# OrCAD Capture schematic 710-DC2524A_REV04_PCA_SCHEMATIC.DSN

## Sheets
1 LTC5555 - Page 2: size Custom; note: PROGRAMMABLE GAIN MIXER
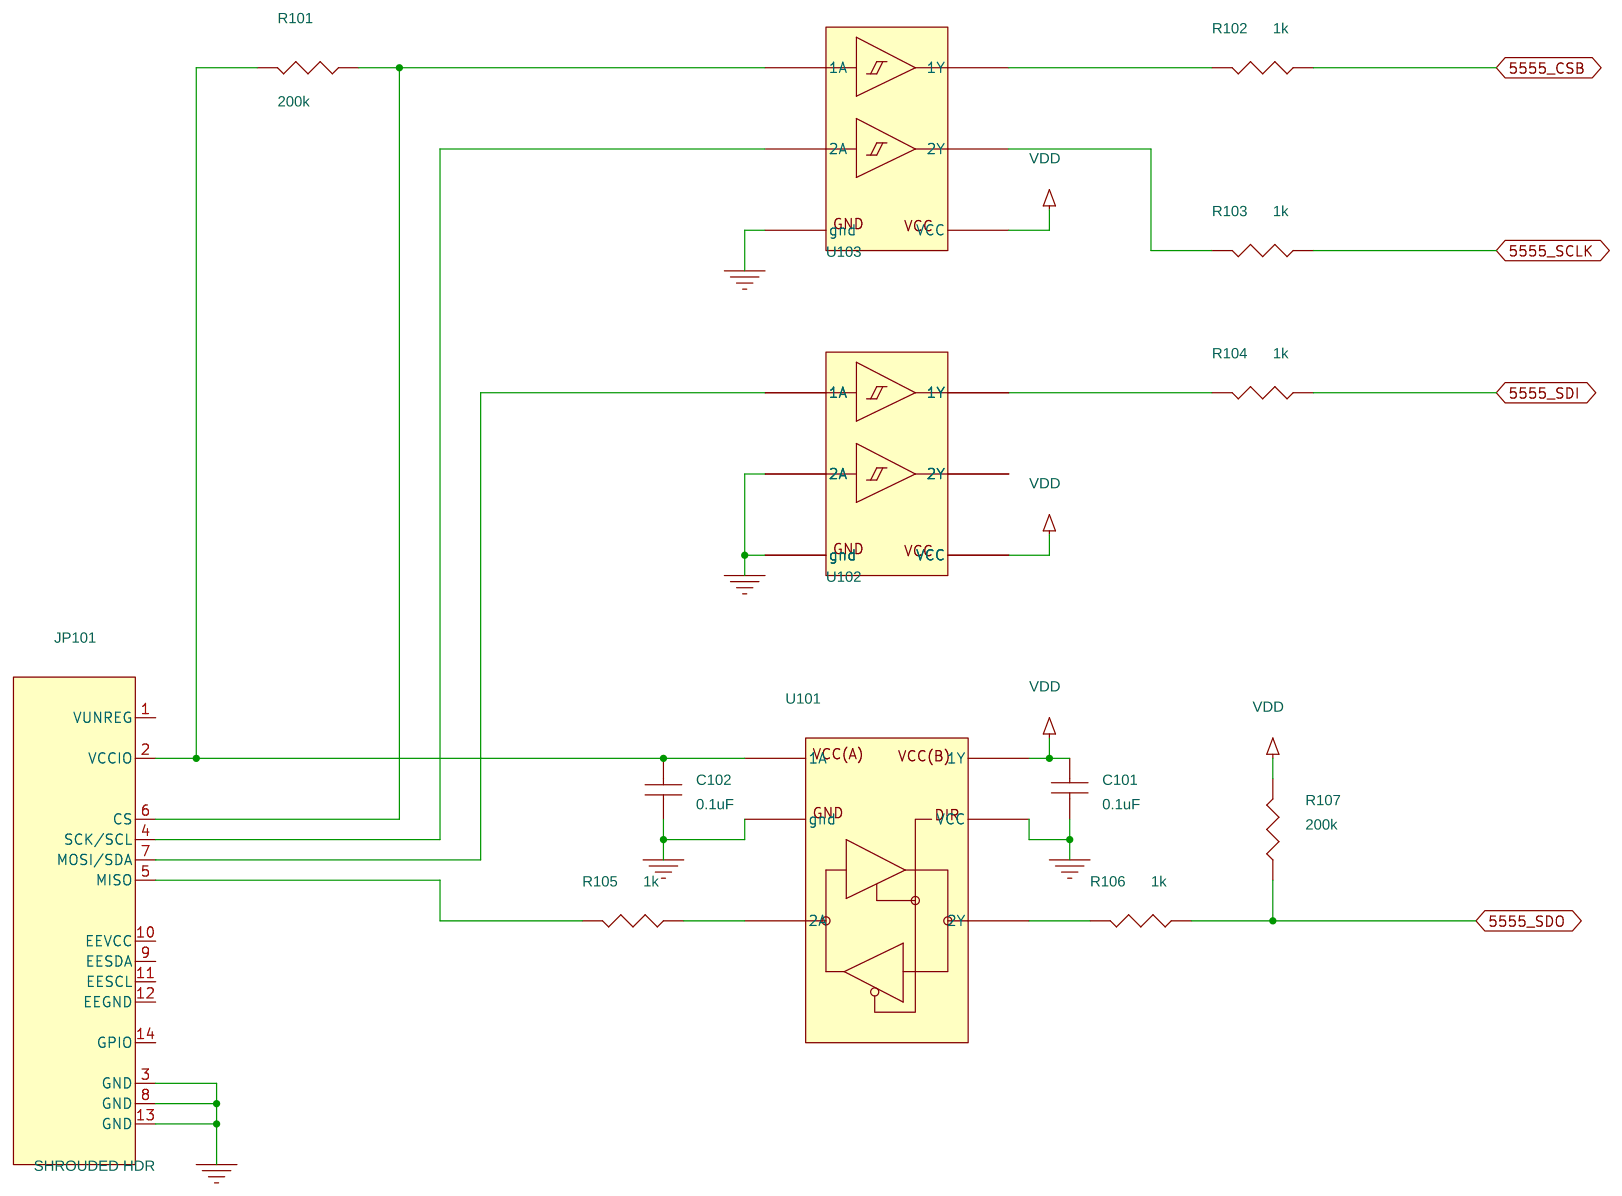
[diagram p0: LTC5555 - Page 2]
2 LTC5555 - Page 1: size Custom
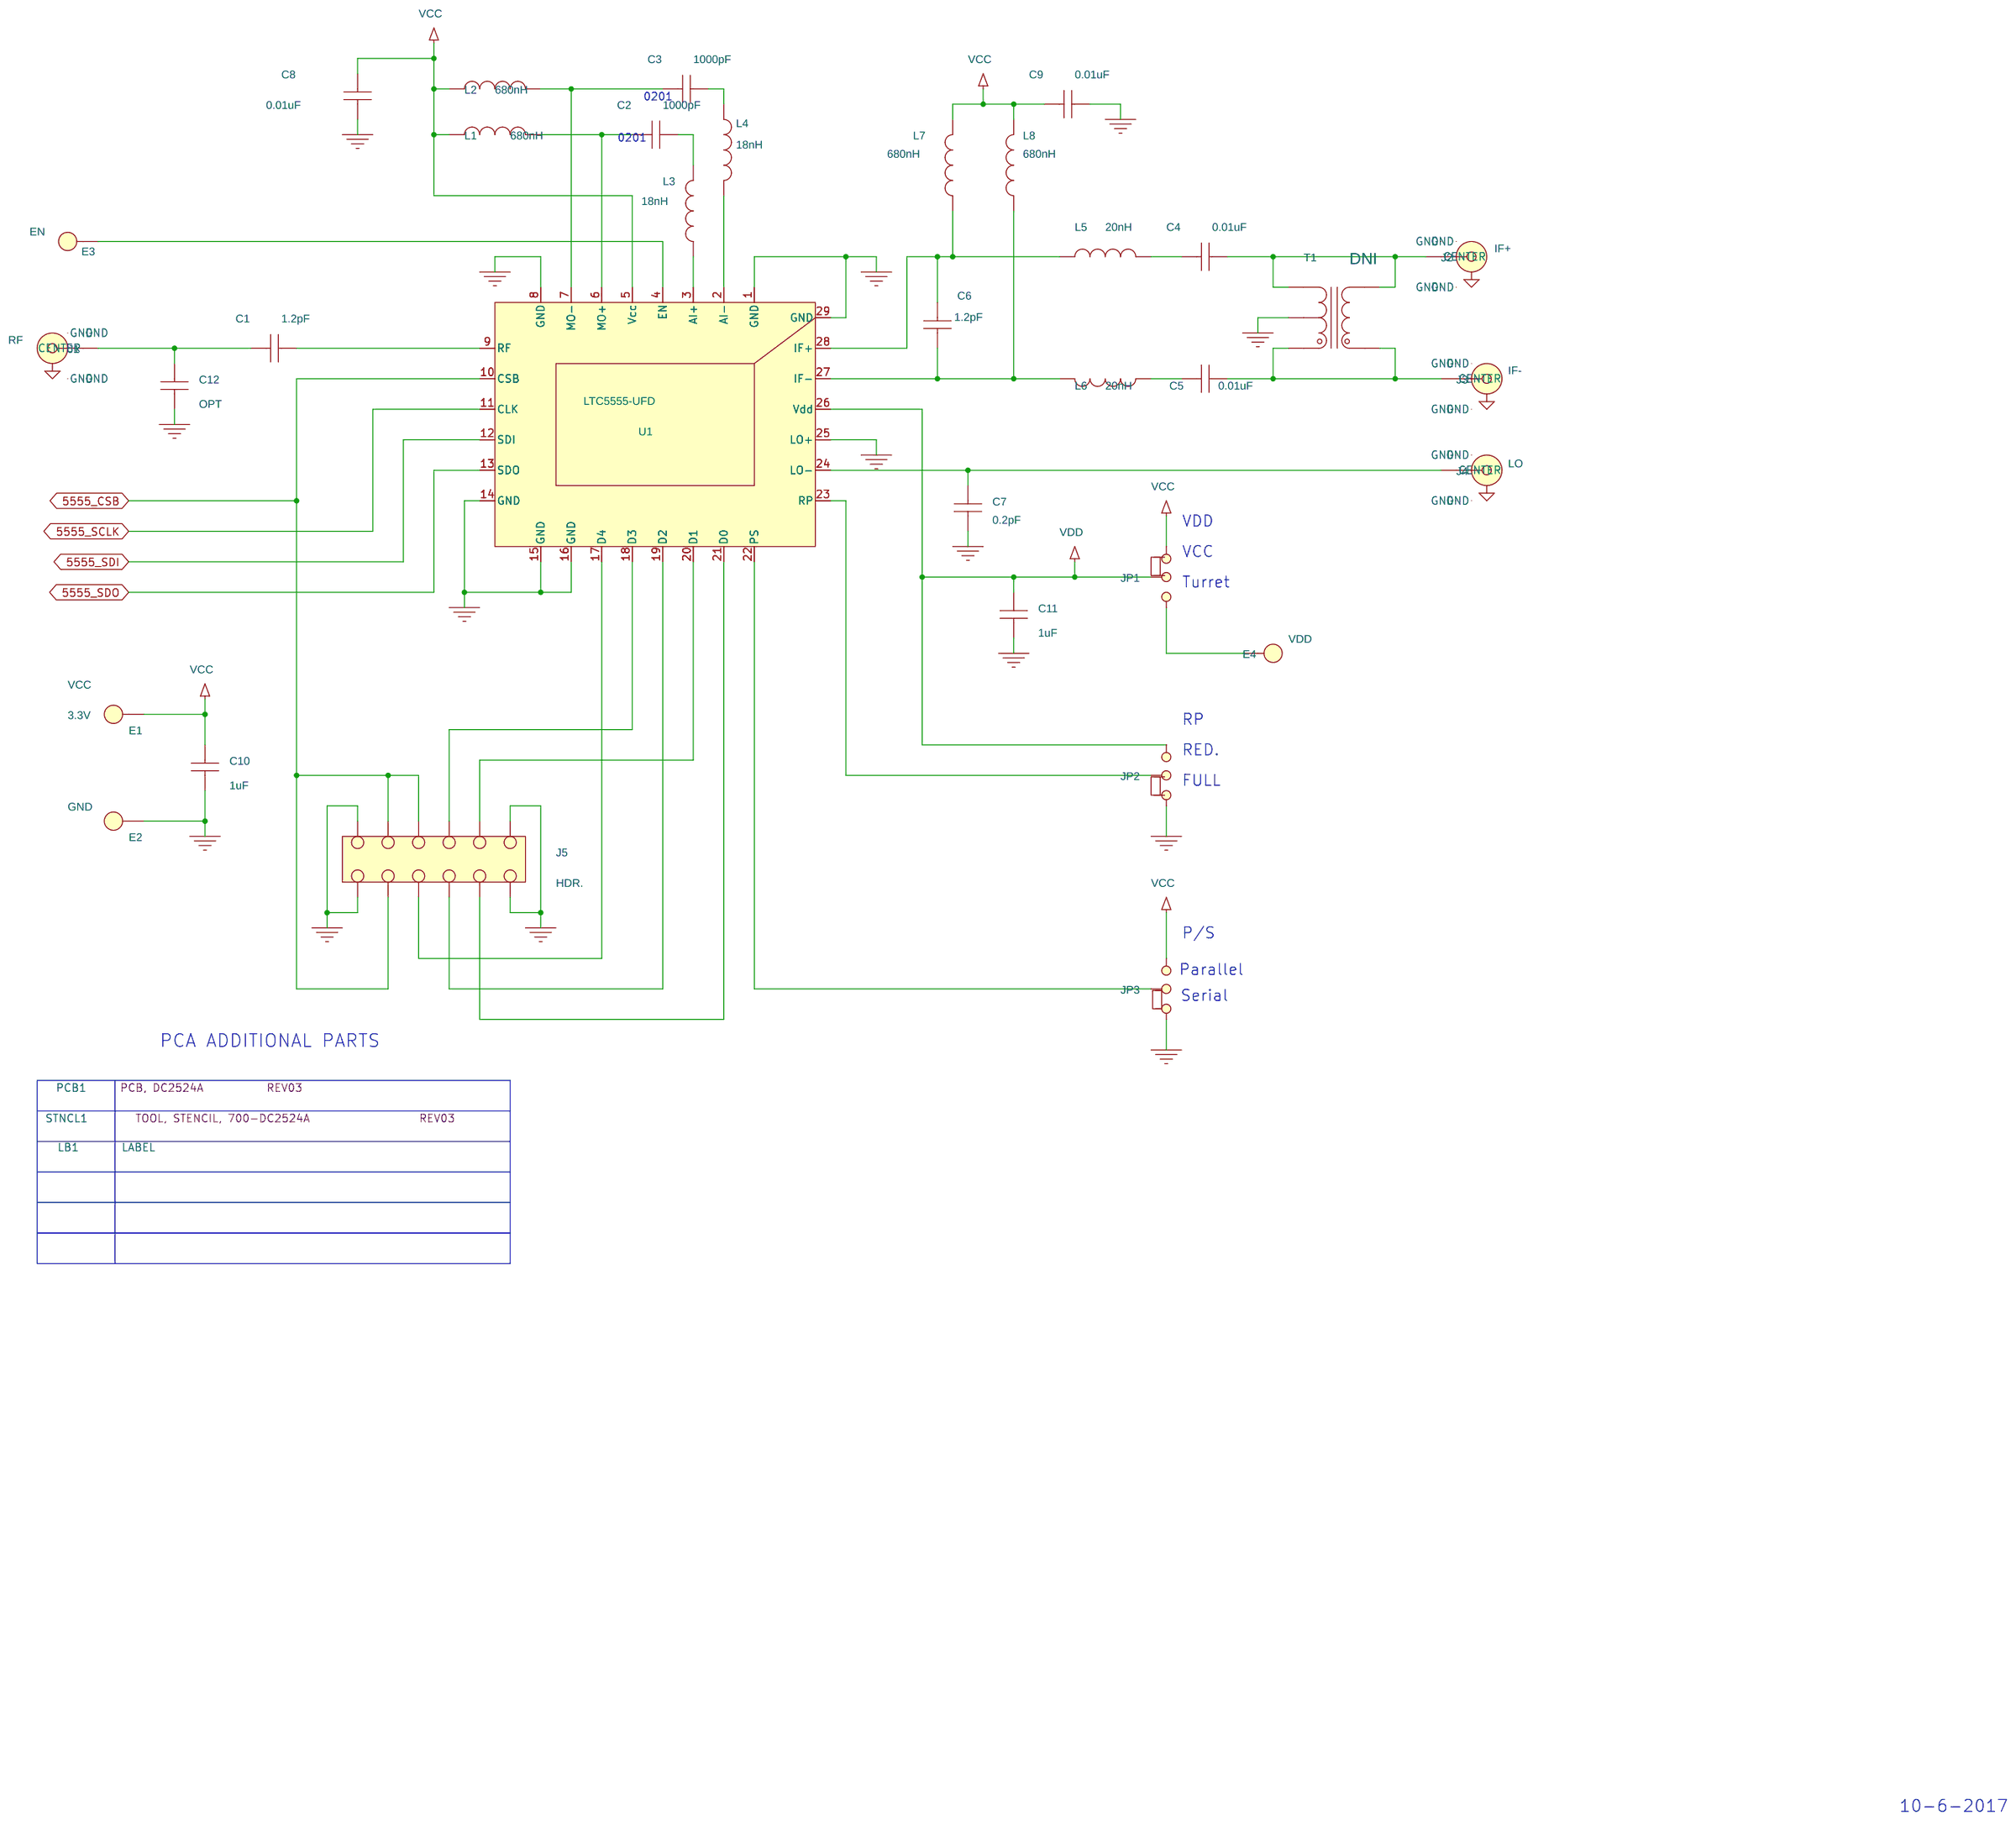
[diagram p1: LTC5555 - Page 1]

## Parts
sheet LTC5555 - Page 1
C1  1.2pF  [CC0402N]
C2  1000pF  [CC0201N]
C3  1000pF  [CC0201N]
C4  0.01uF  [CC0402N]
C5  0.01uF  [CC0402N]
C6  1.2pF  [CC0402N]
C7  0.2pF  [CC0201N]
C8  0.01uF  [CC0402N]
C9  0.01uF  [CC0402N]
C10  1uF  [CC0603N]
C11  1uF  [CC0603N]
C12  OPT  [CC0402N]
E1  TEST POINT  [MILLMAX2308]
E2  TEST POINT  [MILLMAX2308]
E3  TEST POINT  [MILLMAX2308]
E4  TEST POINT  [MILLMAX2308]
J1  SMA  [EMERSON_142-0701-851]
J2  SMA  [EMERSON_142-0701-851]
J3  SMA  [EMERSON_142-0701-851]
J4  SMA  [EMERSON_142-0701-851]
J5  HDR.  [HDR2X6-100-SM]
JP1  HDR.  [HD1X3-079]
JP2  HDR.  [HD1X3-079]
JP3  HDR.  [HD1X3-079]
L1  680nH  [IND0603N]
L2  680nH  [IND0603N]
L3  18nH  [IND0402N]
L4  18nH  [IND0402N]
L5  20nH  [IND0402N]
L6  20nH  [IND0402N]
L7  680nH  [IND0603N]
L8  680nH  [IND0603N]
LB1  LABEL  [895-0154_REV01]
PCB1  PCB, DC2524A
STNCL1  TOOL, STENCIL, 700-DC2524A
T1  TC4-1W-7ALN+  [MINI-CIRCUITS-AT224-1]
U1  LTC5555-UFD  [LTC-UFD-28-1712]
XJP1  SHUNT
XJP2  SHUNT
XJP3  SHUNT
sheet LTC5555 - Page 2
C101  0.1uF  [CC0402N]
C102  0.1uF  [CC0402N]
JP101  SHROUDED HDR  [HD2X7-079-MOLEX]
R101  200k  [CR0402N]
R102  1k  [CR0402N]
R103  1k  [CR0402N]
R104  1k  [CR0402N]
R105  1k  [CR0402N]
R106  1k  [CR0402N]
R107  200k  [CR0402N]
U101  74LVC1T45GW  [SOT363-6N]
U102  NC7WZ17P6X  [SC70-6]
U103  NC7WZ17P6X  [SC70-6]

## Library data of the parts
C1 C6 = CAP: CAP.,1.2pF,C0G,50V,+/-0.05pF,0402; CLASS: DISCRETE; Dielectric Type: C0G; FPLIST: CC0402N,CC0402L,CC0402M; Inventory Qty: 4718; Manufacturer: MURATA; Manufacturer PN: GJM1555C1H1R2WB01D; PART_NUMBER: 150-2024; Package Size: 0402; Rated Voltage: 50V; Tolerance: +/-0.05pF; UserField01: High Q
C2 C3 = CAP: CAP.,1000pF,X7R,50V,10%,0201; CLASS: DISCRETE; Dielectric Type: X7R; FPLIST: CC0201N,CC0201L,CC0201M; Inventory Qty: 388; Manufacturer: MURATA; Manufacturer PN: GRM033R71H102KA12D; PART_NUMBER: 150-2256; Package Size: 0201; Rated Voltage: 50V; Tolerance: 10%
C4 C5 C8 C9 = CAP: CAP.,0.01uF,X7R,50V,10%,0402; CLASS: DISCRETE; Dielectric Type: X7R; FPLIST: CC0402N,CC0402L,CC0402M; Inventory Qty: 63534; Manufacturer: KEMET; Manufacturer PN: C0402C103K5RAC7867; PART_NUMBER: 150-0041; Package Size: 0402; Rated Voltage: 50V; Tolerance: 10%
C7 = CAP: CAP.,0.2pF,C0G,50V,+/-0.05pF,0201; CLASS: DISCRETE; Dielectric Type: C0G; FPLIST: CC0201N,CC0201L,CC0201M; Inventory Qty: 4694; Manufacturer: MURATA; Manufacturer PN: GJM0335C1HR20WB01D; PART_NUMBER: 150-2492; Package Size: 0201; Rated Voltage: 50V; Tolerance: +/-0.05pF; UserField01: HIGH Q, DERATING
C10 C11 = CAP: CAP.,1uF,X5R,50V,10%,0603; CLASS: DISCRETE; Dielectric Type: X5R; FPLIST: CC0603N,CC0603L,CC0603M; Inventory Qty: 12670; Manufacturer: AVX; Manufacturer PN: 06035D105KAT2A; PART_NUMBER: 150-3292; Package Size: 0603; Package Type: SMD; Rated Voltage: 50V; Tolerance: 10%; UserField01: NO SUB ALLOWED
C12 = CAP: CAP., OPTION, 0402; CLASS: DISCRETE; FPLIST: CC0402N,CC0402L,CC0402M; PART_NUMBER: 150-3148; Package Size: 0402; Package Type: SMD
E1 = TEST_POINT_.156_MILL-MAX_2308: TEST POINT,TURRET,0.064" MTG. HOLE,PCB 0.062" THK; 1: VCC; 2: 3.3V; CLASS: IO; Inventory Qty: 771617; Manufacturer: MILL-MAX; Manufacturer PN: 2308-2-00-80-00-00-07-0; PART_NUMBER: 260-0004
E2 = TEST_POINT_.156_MILL-MAX_2308: TEST POINT,TURRET,0.064" MTG. HOLE,PCB 0.062" THK; 1: GND; CLASS: IO; Inventory Qty: 771617; Manufacturer: MILL-MAX; Manufacturer PN: 2308-2-00-80-00-00-07-0; PART_NUMBER: 260-0004
E3 = TEST_POINT_.156_MILL-MAX_2308: TEST POINT,TURRET,0.064" MTG. HOLE,PCB 0.062" THK; 1: EN; CLASS: IO; Inventory Qty: 771617; Manufacturer: MILL-MAX; Manufacturer PN: 2308-2-00-80-00-00-07-0; PART_NUMBER: 260-0004
E4 = TEST_POINT_.156_MILL-MAX_2308: TEST POINT,TURRET,0.064" MTG. HOLE,PCB 0.062" THK; 1: VDD; CLASS: IO; Inventory Qty: 771617; Manufacturer: MILL-MAX; Manufacturer PN: 2308-2-00-80-00-00-07-0; PART_NUMBER: 260-0004
J1 = CONN_SMA_5PIN: CONN.,SMA,JACK,RCPT,END LAUNCH,STR,50 OHMS; 1: RF; CLASS: IO; FPLIST: EMERSON_142-0701-851,SMA-CINCH-142-0761-881_142-0701-851; Inventory Qty: 29695; Manufacturer: CINCH/ BEL; Manufacturer PN: 142-0701-851; PART_NUMBER: 250-0446
J2 = CONN_SMA_5PIN: CONN.,SMA,JACK,RCPT,END LAUNCH,STR,50 OHMS; 1: IF+; CLASS: IO; FPLIST: EMERSON_142-0701-851,SMA-CINCH-142-0761-881_142-0701-851; Inventory Qty: 29695; Manufacturer: CINCH/ BEL; Manufacturer PN: 142-0701-851; PART_NUMBER: 250-0446
J3 = CONN_SMA_5PIN: CONN.,SMA,JACK,RCPT,END LAUNCH,STR,50 OHMS; 1: IF-; CLASS: IO; FPLIST: EMERSON_142-0701-851,SMA-CINCH-142-0761-881_142-0701-851; Inventory Qty: 29695; Manufacturer: CINCH/ BEL; Manufacturer PN: 142-0701-851; PART_NUMBER: 250-0446
J4 = CONN_SMA_5PIN: CONN.,SMA,JACK,RCPT,END LAUNCH,STR,50 OHMS; 1: LO; CLASS: IO; FPLIST: EMERSON_142-0701-851,SMA-CINCH-142-0761-881_142-0701-851; Inventory Qty: 29695; Manufacturer: CINCH/ BEL; Manufacturer PN: 142-0701-851; PART_NUMBER: 250-0446
J5 = HDR2X6: CONN.,HDR.,MALE,2x6,2.54mm,VERT,STR,THT,30u" Au; CLASS: IO; Inventory Qty: 2694; Manufacturer: SAMTEC; Manufacturer PN: TSW-106-07-S-D; PART_NUMBER: 250-0740
JP1-JP3 = HDR3X1_A: CONN.,HDR.,MALE,1x3,2mm,VERT,STR,THT,10u" Au; CLASS: IO; Inventory Qty: 34990; Manufacturer: SAMTEC; Manufacturer PN: TMM-103-02-L-S; PART_NUMBER: 250-0422
L1 L2 L7 L8 = IND: IND.,680nH,RF FERRITE,5%,0603; CLASS: DISCRETE; Inventory Qty: 276; Manufacturer: COILCRAFT; Manufacturer PN: 0603AF-681XJEU; PART_NUMBER: 200-0286; Package Size: 0603; Tolerance: 5%
L3 L4 = IND: IND.,18nH,RF CER.,2%,0402; CLASS: DISCRETE; Inventory Qty: 1388; Manufacturer: COILCRAFT; Manufacturer PN: 0402HP-18NXGLU; PART_NUMBER: 200-0537; Package Size: 0402; Tolerance: 2%
L5 L6 = IND: IND.,20nH,RF, CER.,2%,0402; CLASS: DISCRETE; FPLIST: IND0402N,IND0402L,IND0402M; Inventory Qty: 2388; Manufacturer: COILCRAFT; Manufacturer PN: 0402HP-20NXGLU; PART_NUMBER: 200-0536; Package Size: 0402; Tolerance: 2%
LB1 = BLANK_LABEL: LABEL SPEC, DEMO BOARD SERIAL NUMBER; Inventory Qty: 0; Manufacturer: BRADY; Manufacturer PN: THT-96-717-10; PART_NUMBER: 895-0154
PCB1 = BLANK_PCB_PART: BOM Notes: REV03; CLASS: DISCRETE; Inventory Qty: 0; Manufacturer: MAO BANG; Manufacturer PN: 600-DC2524A; PART_NUMBER: 600-DC2524A
STNCL1 = BLANK_STENCIL_PART: BOM Notes: REV03; CLASS: DISCRETE; Inventory Qty: 0; Manufacturer: LINEAR TECH.; Manufacturer PN: 830-DC2524A; PART_NUMBER: 830-DC2524A
T1 = TRANS-TC4-1W-7ALN+: XFMR,RF,CASE STYLE: AT224-1, 5 to 500 MHz; 1: DNI; BOM NOTES: NO STUFF; CLASS: DISCRETE; Inventory Qty: 0; Manufacturer: MINI-CIRCUITS; PART_NUMBER: 410-0101
U1 = LTC5555-UFD: IC,Prgm Gain Downconverting Mixer,QFN-28,1.5GHz to 7GHz; CLASS: IC; Inventory Qty: 0; Manufacturer: ANALOG DEVICES; Manufacturer PN: LTC5555IUFD#PBF; PART_NUMBER: LTC5555IUFD#PBF; Package Type: QFN-28
XJP1-XJP3 = SHUNT_2MM_B: CONN.,SHUNT,FEMALE,2-POS,2mm; CLASS: IO; Inventory Qty: 98031; Manufacturer: SAMTEC; Manufacturer PN: 2SN-BK-G; PART_NUMBER: 250-0419
C101 C102 = CAP: CAP.,0.1uF,X7R,50V,10%,0402; CLASS: DISCRETE; Dielectric Type: X7R; FPLIST: CC0402N,CC0402L,CC0402M; Inventory Qty: 320056; Manufacturer: AVX; Manufacturer PN: 04025C104KAT2A; PART_NUMBER: 150-3240; Package Size: 0402; Package Type: SMD; Rated Voltage: 50V; Tolerance: 10%
JP101 = CONN_2X7_.079_MOLEX_RIBBON_A: CONN.,SHROUDED HDR,MALE,2x7,2mm,VERT,STR,THT; CLASS: IO; Inventory Qty: 22855; Manufacturer: MOLEX; Manufacturer PN: 87831-1420; PART_NUMBER: 250-0403
R101 R107 = RES: RES.,200k OHMS,1%,1/16W,0402; CLASS: DISCRETE; FPLIST: CR0402N,CR0402L,CR0402M; Inventory Qty: 78908; Manufacturer: PANASONIC; Manufacturer PN: ERJ2RKF2003X; PART_NUMBER: 100-0329; Package Size: 0402; Rated Power: 1/16W; Temperature Coefficient: 100ppm/C; Tolerance: 1%
R102-R106 = RES: RES.,1k OHM,1%,1/16W,0402,AEC-Q200; CLASS: DISCRETE; FPLIST: CR0402N,CR0402L,CR0402M; Inventory Qty: 112734; Manufacturer: VISHAY; Manufacturer PN: CRCW04021K00FKED; PART_NUMBER: 100-2456; Package Size: 0402; Rated Power: 1/16W; Temperature Coefficient: 100ppm/C; Tolerance: 1%
U101 = 74LVC1T45: IC,Dual Supply Transceiver,SOT363-6 (SC-88),Single Bit, 3-State Outputs; CLASS: IC; Inventory Qty: 7574; Manufacturer: NEXPERIA; Manufacturer PN: 74LVC1T45GW,125; PART_NUMBER: 280-8080; Package Type: SOT363-6 (SC-88)
U102 U103 = NC7WZ17: IC,TinyLogic UHS Dual Buffer,SC70-6; CLASS: IC; Inventory Qty: 7852; Manufacturer: FAIRCHILD SEMI; PART_NUMBER: 280-0294

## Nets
GND: C7.2 C8.2 C9.1 C10.2 C11.2 C12.2 C101.2 C102.1 E2.1(A) J1.2(GND) J1.3(GND) J1.4(GND) J1.5(GND) J2.2(GND) J2.3(GND) J2.4(GND) J2.5(GND) J3.2(GND) J3.3(GND) J3.4(GND) J3.5(GND) J4.2(GND) J4.3(GND) J4.4(GND) J4.5(GND) J5.1 J5.2 J5.11 J5.12 JP2.3 JP3.3 JP101.3(GND) JP101.8(GND) JP101.13(GND) T1.2 U1.1(GND) U1.8(GND) U1.14(GND) U1.15(GND) U1.16(GND) U1.25(LO+) U1.29(GND) U101.2(gnd) U101.5(VCC) U102.2(gnd) U102.3(2A) U103.2(gnd)
VCC: C8.1 C9.2 C10.1 E1.1(A) JP1.1 JP3.1 L1.1 L2.1 L7.2 L8.2 U1.5(Vcc)
VDD: C11.1 C101.1 JP1.2 JP2.1 R107.1 U1.26(Vdd) U101.6(1Y) U102.5(VCC) U103.5(VCC)
5555_CSB: J5.3 J5.4 J5.5 R102.2 U1.10(CSB)
5555_SCLK: R103.2 U1.11(CLK)
5555_SDI: R104.2 U1.12(SDI)
5555_SDO: R106.2 R107.2 U1.13(SDO)
N00468: C2.2 L1.2 U1.6(MO+)
N00477: C3.2 L2.2 U1.7(MO-)
N00541: C3.1 L4.1
N00565: C2.1 L3.1
N00666: C1.2 C12.1 J1.1(CENTER)
N36681: E3.1(A) U1.4(EN)
N37040: JP2.2 U1.23(RP)
N37064: JP3.2 U1.22(PS)
N37948: C6.2 L6.1 L8.1 U1.27(IF-)
N37955: C6.1 L5.1 L7.1 U1.28(IF+)
N39008: C5.1 J3.1(CENTER) T1.1 T1.6
N39012: C4.1 J2.1(CENTER) T1.3 T1.4
N39016: C7.1 J4.1(CENTER) U1.24(LO-)
N87923: C5.2 L6.2
N87931: C4.2 L5.2
N89144: E4.1(A) JP1.3
N91808: J5.9 U1.20(D1)
N91812: J5.8 U1.19(D2)
N92331: J5.10 U1.21(D0)
N112908: R103.1 U103.4(2Y)
N112912: C102.2 JP101.2(VCCIO) R101.1 U101.1(1A)
N112916: JP101.7(MOSI/SDA) U102.1(1A)
N113120: R105.2 U101.3(2A)
N113144: R102.1 U103.6(1Y)
N113164: JP101.6(CS) R101.2 U103.1(1A)
N113248: JP101.4(SCK/SCL) U103.3(2A)
N113484: R106.1 U101.4(2Y)
N113662: R104.1 U102.6(1Y)
N151175: C1.1 U1.9(RF)
N151375: J5.7 U1.18(D3)
N151381: J5.6 U1.17(D4)
N151664: L4.2 U1.2(AI-)
N158792: L3.2 U1.3(AI+)
N16780000: JP101.5(MISO) R105.1

Not connected (* = marked no-connect by the designer): JP101 1(VUNREG) 9(EESDA) 10(EEVCC) 11(EESCL) 12(EEGND) 14(GPIO); U102 4(2Y)

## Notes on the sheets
sheet 2
- 0201
- 0201
- VDD
- VCC
- Turret
- RP
- RED.
- FULL
- P/S
- Parallel
- Serial
- PCA ADDITIONAL PARTS
- 10-6-2017
